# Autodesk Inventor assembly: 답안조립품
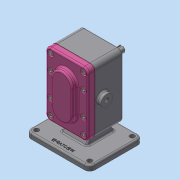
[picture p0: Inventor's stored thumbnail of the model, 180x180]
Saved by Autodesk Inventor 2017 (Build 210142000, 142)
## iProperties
Part Number: 답안조립품
Material: 일반
Document SubType Name: Assembly
Designer: MRC
Author: MRC
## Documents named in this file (11)
- C:\Users\MRC\Desktop\700407V1053\답안조립품.iam
- C:\Users\MRC\Desktop\700407V1053\본체.ipt
- C:\Users\MRC\Desktop\700407V1053\Ű 6 x 6 x 18.ipt
- C:\Users\MRC\Desktop\700407V1053\개스킷.ipt
- C:\Users\MRC\Desktop\700407V1053\메인축.ipt
- C:\Users\MRC\Desktop\700407V1053\베어링부시.ipt
- C:\Users\MRC\Desktop\700407V1053\볼트 M5.ipt
- C:\Users\MRC\Desktop\700407V1053\서브축.ipt
- C:\Users\MRC\Desktop\700407V1053\스퍼기어.ipt
- C:\Users\MRC\Desktop\700407V1053\오일 실 16 28 7.ipt
- C:\Users\MRC\Desktop\700407V1053\커버.ipt
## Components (3 placed, 2 different names)
1. Ű 6 x 6 x 18:1
2. 개스킷:1
3. Ű 6 x 6 x 18:2
